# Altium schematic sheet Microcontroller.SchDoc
size A; SheetNumber: 2; SheetTotal: 4
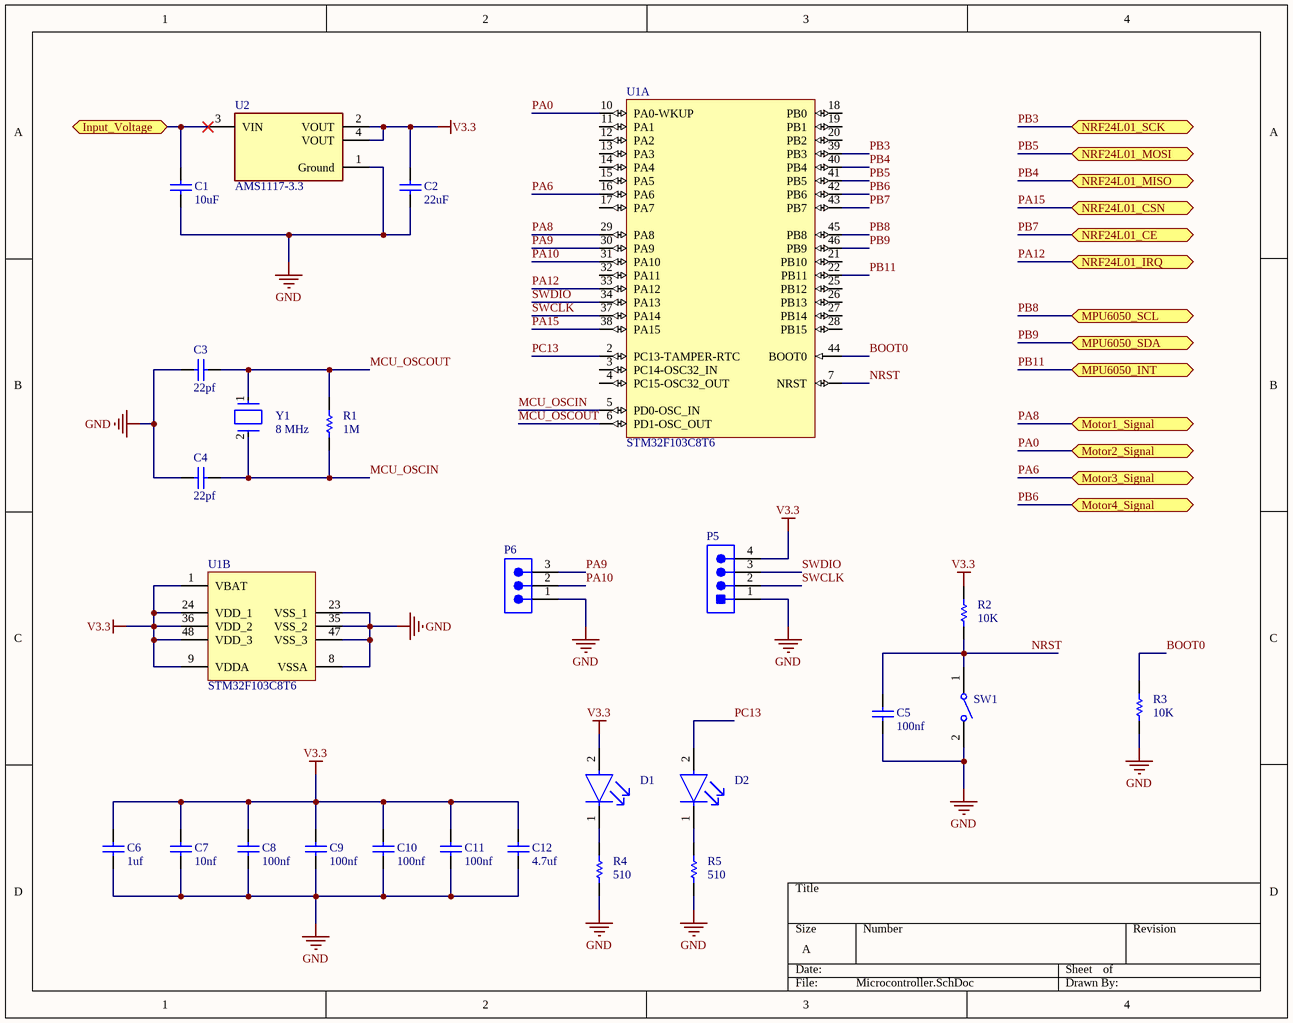
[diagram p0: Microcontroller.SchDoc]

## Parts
C1  value 10uF  [CAPC1206(3216)190_N]  (hidden comment: CAP 1206)
C2  value 22uF  [CAPC1206(3216)190_N]  (hidden comment: CAP 1206)
C3  value 22pf  [CAPC1206(3216)190_N]  (hidden comment: CAP 1206)
C4  value 22pf  [CAPC1206(3216)190_N]  (hidden comment: CAP 1206)
C5  value 100nf  [CAPC1206(3216)190_N]  (hidden comment: CAP 1206)
C6  value 1uf  [CAPC1206(3216)190_N]  (hidden comment: CAP 1206)
C7  value 10nf  [CAPC1206(3216)190_N]  (hidden comment: CAP 1206)
C8  value 100nf  [CAPC1206(3216)190_N]  (hidden comment: CAP 1206)
C9  value 100nf  [CAPC1206(3216)190_N]  (hidden comment: CAP 1206)
C10  value 100nf  [CAPC1206(3216)190_N]  (hidden comment: CAP 1206)
C11  value 100nf  [CAPC1206(3216)190_N]  (hidden comment: CAP 1206)
C12  value 4.7uf  [CAPC1206(3216)190_N]  (hidden comment: CAP 1206)
D1  Power  [FP-CMD15-21-MFG]  (value not drawn)
D2  Status  [FP-CMD15-21-MFG]  (value not drawn)
P5  Program Port  [TECO-280371-2_V]  (value not drawn)
P6  Serial Port  [61900311121]  (value not drawn)
R1  value 1M  [RESC3216X70X50NL05T20]  (hidden comment: ERJ-8GEY0R00V)
R2  value 10K  [RESC3216X70X50NL05T20]  (hidden comment: ERJ-8GEY0R00V)
R3  value 10K  [RESC3216X70X50NL05T20]  (hidden comment: ERJ-8GEY0R00V)
R4  value 510  [RESC3216X70X50NL05T20]  (hidden comment: ERJ-8GEY0R00V)
R5  value 510  [RESC3216X70X50NL05T20]  (hidden comment: ERJ-8GEY0R00V)
SW1  FSMSM  [TECO-FSMSM-2_V]  (value not drawn)
U1  STM32F103C8T6  [STM-LQFP48_L]  (parts A,B of 2)
U2  AMS1117-3.3  [FP-AMS1117-IPC_C]
Y1  Operating Frequency: 8 MHz  [FP-ABLS-MFG]  (hidden comment: ABLS-8.000MHZ-B2-T)

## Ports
Input_Voltage (bidir, see General[2B], General[2C], General[3B], General[3C]), Motor1_Signal (bidir, see General[2B]), Motor2_Signal (bidir, see General[3B]), Motor3_Signal (bidir, see General[2C]), Motor4_Signal (bidir, see General[3C]), MPU6050_INT (bidir, see MPU6050[3B]), MPU6050_SCL (bidir, see MPU6050[1B]), MPU6050_SDA (bidir, see MPU6050[1B]), NRF24L01_CE (bidir, see NRF24L01[2B]), NRF24L01_CSN (bidir, see NRF24L01[2B]), NRF24L01_IRQ (bidir, see NRF24L01[4B]), NRF24L01_MISO (bidir, see NRF24L01[2B]), NRF24L01_MOSI (bidir, see NRF24L01[2B]), NRF24L01_SCK (bidir, see NRF24L01[2A])

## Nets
GND: C1.1 C2.1 C3.2 C4.2 C5.1 C6.1 C7.1 C8.1 C9.1 C10.1 C11.1 C12.1 P5.1 P6.1 R3.1 R4.1 R5.1 SW1.2 U1.8(VSSA) U1.23(VSS_1) U1.35(VSS_2) U1.47(VSS_3) U2.1(Ground)
V3.3: C2.2 C6.2 C7.2 C8.2 C9.2 C10.2 C11.2 C12.2 D1.2(A) P5.4 R2.2 U1.1(VBAT) U1.9(VDDA) U1.24(VDD_1) U1.36(VDD_2) U1.48(VDD_3) U2.2(VOUT) U2.4(VOUT)
BOOT0: R3.2 U1.44(BOOT0)
Input_Voltage: C1.2 U2.3(VIN) ; port Input_Voltage
MCU_OSCIN: C4.1 R1.1 U1.5(PD0-OSC_IN) Y1.2
MCU_OSCOUT: C3.1 R1.2 U1.6(PD1-OSC_OUT) Y1.1
NRST: C5.2 R2.1 SW1.1 U1.7(NRST)
PA0: U1.10(PA0-WKUP) ; port Motor2_Signal
PA6: U1.16(PA6) ; port Motor3_Signal
PA8: U1.29(PA8) ; port Motor1_Signal
PA9: P6.3 U1.30(PA9)
PA10: P6.2 U1.31(PA10)
PA12: U1.33(PA12) ; port NRF24L01_IRQ
PA15: U1.38(PA15) ; port NRF24L01_CSN
PB3: U1.39(PB3) ; port NRF24L01_SCK
PB4: U1.40(PB4) ; port NRF24L01_MISO
PB5: U1.41(PB5) ; port NRF24L01_MOSI
PB6: U1.42(PB6) ; port Motor4_Signal
PB7: U1.43(PB7) ; port NRF24L01_CE
PB8: U1.45(PB8) ; port MPU6050_SCL
PB9: U1.46(PB9) ; port MPU6050_SDA
PB11: U1.22(PB11) ; port MPU6050_INT
PC13: D2.2(A) U1.2(PC13-TAMPER-RTC)
SWCLK: P5.2 U1.37(PA14)
SWDIO: P5.3 U1.34(PA13)
NetD1_1: D1.1(C) R4.2
NetD2_1: D2.1(C) R5.2

Not connected (* = marked no-connect by the designer): U1 3(PC14-OSC32_IN) 4(PC15-OSC32_OUT) 11(PA1) 12(PA2) 13(PA3) 14(PA4) 15(PA5) 17(PA7) 18(PB0) 19(PB1) 20(PB2) 21(PB10) 25(PB12) 26(PB13) 27(PB14) 28(PB15) 32(PA11)

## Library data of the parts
C1-C12 = CMP-1037-04961-1: Tolerance: Â±10%; Case-EIA: 1206; Case-Metric: 3216; Rated Voltage: 6.3 V
D1 D2 = CMP-53976-000002-1: LED RED DIFFUSED 1206 SMD; Manufacturer: VCC; Manufacturer Part Number: CMD15-21VRD/TR8; Led Orientation: Top View; Peak Emmision Wavelength: 640nm; Forward Current: 20mA; Power Dissipation: 105mW; Luminous Intensity: 4mcd; Forward Voltage: 2V; Reverse Voltage: 5V
P5 = CMP-2000-05548-1: Male Header, Pitch 2.54 mm, 1 x 4 Position, Height 12.8 mm, Tail Length 3.5 mm, -55 to 105 degC, RoHS, Bulk; Manufacturer: TE Connectivity; Pitch: 0.100"(2.54mm); Connector Type: Header,Shrouded; Other Names: 280371-2-ND / A106401; Number of Positions Loaded: All; Dynamic Catalog: AMPMODUModIISeries; Number of Positions: 4; 3D Model: 280371-2.pdf
P6 = CMP-1502-00585-2: NexarPartId: 18818222; Current Rating: 3A; Voltage Rating: 250V; Number of Positions: 3; Insulation Resistance: 1GΩ; Gender: Male; Pitch: 2.54mm; Connector Type: Male Pin; Contact Resistance: 20mΩ
R1-R5 = CMP-2003-00541-1: Manufacturer: Panasonic
SW1 = CMP-2000-07511-1: FSMSM Push Button Switch, 50 mA, -35 to 85 degC, 2-Pin SMD, RoHS, Bulk; Manufacturer: TE Connectivity; Actuator Length: 1.07mm; Electrical Life: 20000Cycles; Actuator Material: Polyamide; Current Rating: 50mA; Illumination Type: Illuminated; Voltage Rating (DC): 24V; Contact Resistance: 100mOhm; Case\/Package: SMD/SMT; Operating Force: 180gf; Switch Travel: 0.25mm; Max Voltage Rating (DC): 12V; Throw Configuration: SPST
U1 = CMP-0237-00215-3: ARM Cortex-M3 32-bit MCU, 64 KB Flash, 20 KB Internal RAM, 37 I/Os, 48-pin LQFP, -40 to 85 degC, Tray; Supply Voltage(Vcc) min (V): 2; Internal RAM Size (kB): 20; FLASH Size (Prog) (kB): 64; A/D Converter: 2x12-bit (10 Channel); I/Os (High Current): 37; Operating Frequency(F) (Processor speed) (MHz): 72
U2 = CMP-209535-000001-1: LDO Voltage Regulators 1A, 3.3V; Manufacturer: Advanced Monolithic Systems; Dropout Voltage: 1.1V; Output Type: Fixed; Nominal Supply Current: 5mA; Max Power Dissipation: 1.2W; Max Supply Voltage: 15V; Number Of Outputs: 1; Standoff Height: 0.64mm; Max Junction Temp: +125°C
Y1 = CMP-27762-009874-1: CRYSTAL 8.0000MHZ 18PF SMD; ESR (Equivalent Series Resistance): 80R; Frequency Stability: 50ppm; Tolerance: 20ppm; Frequency: 8MHz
